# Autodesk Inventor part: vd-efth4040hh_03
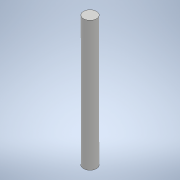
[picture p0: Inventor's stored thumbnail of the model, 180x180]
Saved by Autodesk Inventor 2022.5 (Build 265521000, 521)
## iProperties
Created: 2019-12
Part Number: vd-efth4040hh_03
Material: 一般
Document SubType Name: Modeling
Designer: ImaoCorp
Density: 1 g/cm^3
Appearance: 既定
Author: ImaoCorp
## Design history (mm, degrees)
feature "vd-efth4040hh_03"
node "ソリッド1"
